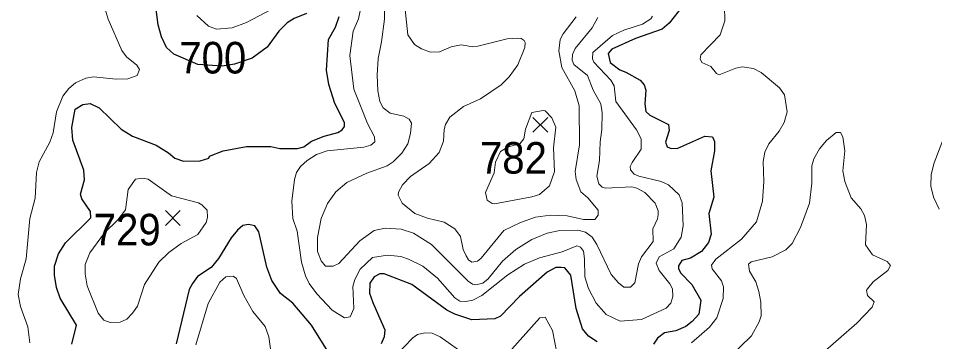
# Model space of a CAD drawing. Extents: x 294.2 to 320.3, y 7482.7 to 7510.7.
# Drawn here: x 312.447 to 314.766, y 7488.425 to 7489.244 of the extents above; entities that cross this region are included whole.
import ezdxf
from ezdxf.enums import TextEntityAlignment as Align

# ---------------------------------------------------------------- set-up
doc = ezdxf.new("R2010")
doc.units = 0
doc.header["$LTSCALE"] = 0.032
for name, color, linetype, lineweight in [('1', 7, 'Continuous', 25), ('2', 7, 'Continuous', 13), ('21', 7, 'Continuous', 25)]:
    doc.layers.add(name, color=color, linetype=linetype, lineweight=lineweight)
doc.layers.add('61', color=7, linetype='Continuous')

msp = doc.modelspace()

# ---------------------------------------------------------------- linework, layer by layer
at = {"layer": '1'}
for points in [[(313.1762, 7489.2559), (313.1449, 7489.2437), (313.1277, 7489.2323), (313.1066, 7489.2118), (313.0768, 7489.1711), (313.0391, 7489.1428), (312.9943, 7489.1278), (312.9632, 7489.1231), (312.9011, 7489.1271), (312.8405, 7489.153), (312.8219, 7489.1703), (312.8091, 7489.1971), (312.8008, 7489.2278), (312.7881, 7489.3261)], [(314.1294, 7489.2755), (314.0944, 7489.2315), (314.0763, 7489.2166), (314.0095, 7489.193), (313.9489, 7489.1663), (313.9403, 7489.1545), (313.9448, 7489.1322), (313.9697, 7489.1135), (313.9844, 7489.1073), (314.0208, 7489.0876), (314.0309, 7489.0755), (314.0357, 7489.0624), (314.0325, 7489.0273), (314.0353, 7489.0081), (314.0456, 7488.9987), (314.0927, 7488.9751), (314.0943, 7488.9602), (314.0849, 7488.9303), (314.0892, 7488.9185), (314.0995, 7488.9145), (314.116, 7488.9153), (314.1844, 7488.9452), (314.204, 7488.9436), (314.2095, 7488.9318), (314.2095, 7488.9082), (314.2001, 7488.8579), (314.2074, 7488.7911), (314.1948, 7488.7502), (314.2005, 7488.6975), (314.1942, 7488.6763), (314.1762, 7488.6535)], [(312.7072, 7488.9635), (312.7363, 7488.9454), (312.7963, 7488.9226), (312.8269, 7488.9037), (312.8434, 7488.8896), (312.8647, 7488.8825), (312.9074, 7488.883), (312.9291, 7488.89), (312.9312, 7488.8948), (312.9658, 7488.9082), (313.0242, 7488.9192), (313.0863, 7488.9192), (313.1091, 7488.9145), (313.1535, 7488.9145), (313.17, 7488.9184), (313.1889, 7488.9326), (313.2211, 7488.9459), (313.2557, 7488.9546), (313.2667, 7488.9617), (313.273, 7488.9703), (313.273, 7488.9798), (313.2481, 7489.0285), (313.2326, 7489.0765), (313.2271, 7489.1127), (313.232, 7489.1906), (313.2501, 7489.2212), (313.2588, 7489.2487)], [(312.5846, 7488.9358), (312.5822, 7488.9673), (312.5909, 7489.0137), (312.6105, 7489.0255), (312.629, 7489.0287), (312.6514, 7489.0177), (312.7072, 7488.9635)], [(312.5827, 7488.4187), (312.5941, 7488.4675), (312.5532, 7488.5351), (312.5438, 7488.5626), (312.5385, 7488.5941), (312.5387, 7488.6166), (312.549, 7488.6481), (312.5665, 7488.6756), (312.6302, 7488.7385), (312.6298, 7488.755), (312.6078, 7488.7872), (312.6047, 7488.799), (312.6149, 7488.8352), (312.6125, 7488.8596), (312.5846, 7488.9358)], [(313.2293, 7488.4023), (313.1888, 7488.4668), (313.1416, 7488.5226), (313.1102, 7488.547), (313.0889, 7488.58), (313.0758, 7488.6138), (313.0557, 7488.7034), (313.0455, 7488.7184), (313.0298, 7488.7223), (313.0156, 7488.7192), (313.0015, 7488.7074), (312.9858, 7488.6885), (312.9535, 7488.6358), (312.9349, 7488.613), (312.9007, 7488.5902), (312.8881, 7488.5729), (312.8794, 7488.5572), (312.8466, 7488.4196)], [(314.1762, 7488.6535), (314.1486, 7488.637), (314.1266, 7488.6307), (314.118, 7488.6173), (314.118, 7488.6102), (314.1235, 7488.5992), (314.1521, 7488.5702)], [(313.9122, 7488.4248), (313.8902, 7488.4389), (313.8747, 7488.4578), (313.8589, 7488.5089), (313.8455, 7488.5938), (313.8306, 7488.6119), (313.8212, 7488.6135), (313.8078, 7488.6135), (313.7854, 7488.6009), (313.7155, 7488.5396), (313.6675, 7488.4901), (313.6528, 7488.483), (313.5949, 7488.4807), (313.5516, 7488.4948), (313.5318, 7488.505), (313.443, 7488.5704), (313.373, 7488.5972), (313.362, 7488.5972), (313.3473, 7488.5893), (313.3368, 7488.5736), (313.3361, 7488.5484), (313.3447, 7488.5248), (313.3531, 7488.505), (313.3745, 7488.455), (313.3729, 7488.4377), (313.3658, 7488.4197)], [(314.1521, 7488.5702), (314.1749, 7488.5301), (314.1694, 7488.4947), (314.1529, 7488.4766), (314.1364, 7488.464), (314.1115, 7488.453), (314.0824, 7488.4475), (314.0651, 7488.4342), (314.0549, 7488.4192)]]:
    msp.add_lwpolyline(points, dxfattribs=at)
at = {"layer": '2'}
for points in [[(312.652, 7489.3185), (312.6743, 7489.2418), (312.7088, 7489.1627), (312.721, 7489.1467), (312.7471, 7489.125), (312.7535, 7489.1147), (312.7478, 7489.0994), (312.7242, 7489.0911), (312.6948, 7489.0898), (312.6374, 7489.0956), (312.6182, 7489.0924), (312.5914, 7489.0809), (312.5748, 7489.0663), (312.5594, 7489.0465), (312.5435, 7489.0069), (312.5352, 7488.9538), (312.5269, 7488.9303), (312.5001, 7488.8805), (312.493, 7488.8536), (312.4899, 7488.7885), (312.4764, 7488.7374), (312.4669, 7488.6353), (312.4522, 7488.5842), (312.447, 7488.5446), (312.4522, 7488.514), (312.4713, 7488.4629), (312.4758, 7488.422)], [(313.3575, 7489.1422), (313.3665, 7489.1844), (313.3735, 7489.2418), (313.3728, 7489.3082)], [(313.1417, 7488.7374), (313.1392, 7488.7809), (313.1462, 7488.8358), (313.1513, 7488.8536), (313.1615, 7488.869), (313.1781, 7488.8842), (313.2018, 7488.8996), (313.2286, 7488.9085), (313.3218, 7488.9181), (313.339, 7488.9232), (313.3493, 7488.9315), (313.3486, 7488.9443), (313.3307, 7488.9775), (313.3128, 7489.0222), (313.2962, 7489.0643), (313.286, 7489.1499), (313.2949, 7489.2112), (313.3077, 7489.2431), (313.3154, 7489.2789)], [(313.4252, 7489.2738), (313.4329, 7489.2023), (313.4495, 7489.1773), (313.4674, 7489.1665), (313.4903, 7489.1582), (313.5134, 7489.1588), (313.5427, 7489.1722), (313.5683, 7489.1767), (313.5976, 7489.1722), (313.6104, 7489.1735), (313.6845, 7489.192), (313.71, 7489.1939), (313.7202, 7489.1933), (313.7272, 7489.1882), (313.7298, 7489.1831), (313.7291, 7489.1703), (313.7112, 7489.1262), (313.6896, 7489.0962), (313.6691, 7489.0758), (313.6168, 7489.04), (313.5734, 7489.0209), (313.5395, 7488.9941), (313.5286, 7488.975), (313.5248, 7488.9622), (313.5235, 7488.9328), (313.512, 7488.904), (313.4871, 7488.876), (313.4393, 7488.8434), (313.4195, 7488.8223), (313.4093, 7488.8038), (313.4086, 7488.7962), (313.4182, 7488.7757), (313.4508, 7488.7496), (313.4827, 7488.7381), (313.5248, 7488.7279), (313.5523, 7488.7112), (313.5663, 7488.6915), (313.5733, 7488.6583), (313.5804, 7488.6429), (313.5861, 7488.6321), (313.5951, 7488.627), (313.6091, 7488.6289), (313.6187, 7488.6366), (313.6755, 7488.7068), (313.7177, 7488.7272), (313.756, 7488.7406), (313.7943, 7488.7457), (313.8364, 7488.7438), (313.8773, 7488.7348), (313.9066, 7488.7348), (313.9149, 7488.7457), (313.9149, 7488.7585), (313.8888, 7488.7891), (313.8709, 7488.8044), (313.8588, 7488.8358), (313.8568, 7488.8562), (313.8677, 7488.9239), (313.867, 7489.0222), (313.8555, 7489.0605), (313.8223, 7489.1193), (313.8153, 7489.1614), (313.8185, 7489.1901), (313.8262, 7489.2048), (313.8588, 7489.2476)], [(314.1512, 7488.422), (314.1965, 7488.4622), (314.215, 7488.4859), (314.231, 7488.5344), (314.2316, 7488.5638), (314.2271, 7488.5791), (314.2035, 7488.6097), (314.2016, 7488.6193), (314.2125, 7488.634), (314.2776, 7488.685), (314.3152, 7488.7285), (314.3306, 7488.7809), (314.3344, 7488.8307), (314.3325, 7488.8817), (314.3363, 7488.9047), (314.3466, 7488.9264), (314.3727, 7488.9583), (314.3855, 7488.9801), (314.3931, 7489.0069), (314.3861, 7489.0503), (314.3734, 7489.0682), (314.3274, 7489.1064), (314.3082, 7489.1167), (314.2795, 7489.1212), (314.2629, 7489.1179), (314.2208, 7489.1007), (314.2144, 7489.1039), (314.1997, 7489.1218), (314.1767, 7489.132), (314.1729, 7489.141), (314.1748, 7489.1518), (314.2233, 7489.2022), (314.2355, 7489.238), (314.2348, 7489.275)], [(313.0868, 7489.2667), (313.0243, 7489.2335), (312.9885, 7489.2195), (312.9489, 7489.2163), (312.9285, 7489.2239), (312.8991, 7489.2508)], [(314.0522, 7489.2495), (314.0477, 7489.2425), (314.0273, 7489.2291), (313.9794, 7489.2144), (313.9513, 7489.2009), (313.9015, 7489.1575), (313.9002, 7489.141), (313.9041, 7489.1333), (313.9469, 7489.0873), (313.9551, 7489.0733), (313.959, 7489.0337), (314.012, 7488.9615), (314.0235, 7488.9392), (314.0235, 7488.913), (314.0011, 7488.8792), (313.996, 7488.869), (313.9967, 7488.86), (314.0056, 7488.8498), (314.0177, 7488.8441), (314.0739, 7488.8306), (314.0931, 7488.8224), (314.1193, 7488.7975), (314.1275, 7488.777), (314.1301, 7488.7183), (314.125, 7488.6902), (314.1065, 7488.6602), (314.0694, 7488.6404), (314.0611, 7488.6238), (314.0688, 7488.6052), (314.0963, 7488.572), (314.1027, 7488.5587), (314.1039, 7488.5395), (314.0982, 7488.5229), (314.0867, 7488.5101), (314.0241, 7488.4814), (313.9705, 7488.4769), (313.9347, 7488.4941), (313.929, 7488.5006), (313.9098, 7488.5229), (313.89, 7488.5599), (313.8811, 7488.5893), (313.8805, 7488.6353), (313.8772, 7488.6544), (313.8702, 7488.6647), (313.8607, 7488.6678), (313.8237, 7488.6525), (313.7662, 7488.6372), (313.7279, 7488.6212), (313.6863, 7488.5944), (313.6206, 7488.542), (313.5976, 7488.5305), (313.5798, 7488.5267), (313.5644, 7488.528), (313.5523, 7488.5363), (313.5082, 7488.5861), (313.4706, 7488.6161), (313.4348, 7488.6346), (313.4156, 7488.641), (313.3818, 7488.6442), (313.3435, 7488.6385), (313.3122, 7488.6091), (313.2988, 7488.5829), (313.2937, 7488.5651), (313.2962, 7488.5089), (313.2867, 7488.4878), (313.2726, 7488.4858), (313.2413, 7488.505)], [(313.9137, 7489.2457), (313.8996, 7489.2195), (313.8568, 7489.1678), (313.8498, 7489.1525), (313.8491, 7489.1377), (313.853, 7489.1269), (313.8881, 7489.0995), (313.9022, 7489.0618), (313.9213, 7489.0273), (313.9245, 7489.0043), (313.9239, 7488.9622), (313.9194, 7488.9315), (313.9181, 7488.8843), (313.9111, 7488.8447), (313.9162, 7488.8249), (313.9251, 7488.8166), (313.9335, 7488.814), (313.9999, 7488.8172), (314.0126, 7488.814), (314.0324, 7488.8032), (314.0586, 7488.7764), (314.0662, 7488.7566), (314.0662, 7488.7464), (314.0649, 7488.7362), (314.0529, 7488.7113), (314.0541, 7488.6787), (314.0241, 7488.6404), (314.0171, 7488.6225), (314.0075, 7488.5746), (313.9966, 7488.5631), (313.9794, 7488.5637), (313.966, 7488.574), (313.9475, 7488.5957), (313.9117, 7488.671), (313.8996, 7488.6896), (313.8824, 7488.7023), (313.8632, 7488.7074), (313.8134, 7488.7062), (313.7853, 7488.6998), (313.747, 7488.6844), (313.7062, 7488.6589), (313.6729, 7488.6289), (313.6359, 7488.5848), (313.6225, 7488.5733), (313.6053, 7488.5695), (313.5964, 7488.5708), (313.5855, 7488.5784), (313.4929, 7488.6717), (313.4469, 7488.6998), (313.4163, 7488.71), (313.3754, 7488.7131), (313.3479, 7488.7068), (313.3115, 7488.6806), (313.2579, 7488.6231), (313.2439, 7488.6161), (313.2247, 7488.6161), (313.2139, 7488.6302), (313.2043, 7488.6532), (313.2043, 7488.6889), (313.2139, 7488.7374), (313.2298, 7488.7751), (313.2509, 7488.8045), (313.2784, 7488.8281), (313.3295, 7488.8523), (313.3805, 7488.8702), (313.3959, 7488.8804), (313.4175, 7488.9022), (313.4329, 7488.9264), (313.4399, 7488.952), (313.4418, 7488.9788), (313.4361, 7488.9884), (313.4227, 7488.9966)], [(313.4227, 7488.9966), (313.3882, 7489.0037), (313.3703, 7489.0177), (313.362, 7489.0337), (313.3569, 7489.0605), (313.355, 7489.1001), (313.3575, 7489.1422)], [(314.4768, 7488.3914), (314.5694, 7488.4718), (314.6083, 7488.5127), (314.6134, 7488.5261), (314.5962, 7488.542), (314.5943, 7488.5554), (314.5968, 7488.5593), (314.6109, 7488.5765), (314.6479, 7488.6059), (314.6543, 7488.618), (314.6466, 7488.6283), (314.609, 7488.6449), (314.5911, 7488.6704), (314.5943, 7488.7221), (314.5892, 7488.7451), (314.5796, 7488.7617), (314.5547, 7488.7898), (314.5387, 7488.8307), (314.5336, 7488.8575), (314.5387, 7488.9086), (314.5336, 7488.9443), (314.5279, 7488.9545), (314.517, 7488.9552), (314.4927, 7488.9347), (314.4749, 7488.9137), (314.4608, 7488.8881), (314.4557, 7488.8702), (314.4551, 7488.8268), (314.4493, 7488.7758), (314.427, 7488.7145), (314.4059, 7488.6736), (314.3899, 7488.6576), (314.3549, 7488.6403), (314.3018, 7488.6276), (314.2955, 7488.6212), (314.2974, 7488.6034), (314.3134, 7488.5765), (314.321, 7488.5523), (314.3267, 7488.5255), (314.3274, 7488.491), (314.3223, 7488.4757), (314.3025, 7488.4405), (314.2457, 7488.3844)], [(314.7954, 7488.9571), (314.7654, 7488.8779), (314.7577, 7488.8485), (314.7571, 7488.8192), (314.7634, 7488.7911), (314.7782, 7488.7604)], [(313.2413, 7488.505), (313.2024, 7488.5465), (313.1833, 7488.5727), (313.1736, 7488.5919), (313.1634, 7488.6263), (313.1532, 7488.7055), (313.1417, 7488.7374)], [(312.8965, 7488.4169), (312.9272, 7488.5216), (312.9572, 7488.5759), (312.9719, 7488.5893), (312.9911, 7488.5912), (312.9993, 7488.5855), (313.0178, 7488.5421), (313.0402, 7488.5018), (313.0722, 7488.4635), (313.0811, 7488.4374), (313.0881, 7488.3888)], [(313.696, 7488.4067), (313.7668, 7488.4858), (313.7802, 7488.4871), (313.7987, 7488.454), (313.8108, 7488.3927)], [(313.3773, 7488.3639), (313.4456, 7488.4354), (313.4571, 7488.4431), (313.4763, 7488.4475), (313.4942, 7488.4469), (313.5146, 7488.4373), (313.5816, 7488.3907)]]:
    msp.add_lwpolyline(points, dxfattribs=at)
for points in [[(313.7664, 7488.798), (313.747, 7488.7917), (313.6525, 7488.7744), (313.6461, 7488.7751), (313.634, 7488.784), (313.6295, 7488.8032), (313.6512, 7488.8524), (313.6545, 7488.8795), (313.6676, 7488.9065), (313.6873, 7488.9188), (313.7168, 7488.9262), (313.7267, 7488.9385), (313.7304, 7488.9635), (313.7472, 7489.0057), (313.7751, 7489.0107), (313.7802, 7489.0101), (313.7972, 7488.9918), (313.8078, 7488.9688), (313.8019, 7488.9162), (313.8044, 7488.8562), (313.7917, 7488.8198)], [(312.6494, 7488.4979), (312.6214, 7488.5663), (312.6163, 7488.597), (312.6163, 7488.6206), (312.6284, 7488.6499), (312.6653, 7488.701), (312.6992, 7488.7336), (312.7181, 7488.7587), (312.7254, 7488.8102), (312.744, 7488.837), (312.7612, 7488.839), (312.7759, 7488.8364), (312.8346, 7488.7943), (312.903, 7488.777), (312.9119, 7488.7719), (312.9246, 7488.7579), (312.9259, 7488.74), (312.9228, 7488.7272), (312.9017, 7488.6965), (312.8595, 7488.6742), (312.8282, 7488.6512), (312.8027, 7488.627), (312.7663, 7488.5701), (312.7484, 7488.5153), (312.7363, 7488.4974), (312.7216, 7488.4827), (312.705, 7488.475), (312.6795, 7488.4737), (312.6635, 7488.4795)]]:
    msp.add_lwpolyline(points, close=True, dxfattribs=at)
at = {"layer": '21'}
for p, q in [((313.7495, 7488.9932), (313.787, 7488.9557)), ((313.787, 7488.9932), (313.7495, 7488.9557)), ((312.8193, 7488.7571), (312.8568, 7488.7196)), ((312.8568, 7488.7571), (312.8193, 7488.7196))]:
    msp.add_line(p, q, dxfattribs=at)

# ---------------------------------------------------------------- texts
at = {"layer": '61', "width": 0.95}
for s, p in [('700', (312.9391, 7489.1043)), ('782', (313.7002, 7488.8507)), ('729', (312.7226, 7488.669))]:
    msp.add_text(s, height=0.08, dxfattribs=at).set_placement(p, align=Align.CENTER)

doc.saveas('drawing.dxf')
